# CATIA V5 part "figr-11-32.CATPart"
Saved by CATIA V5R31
Part number: Part1
Bounding box of the stored display mesh (mm): x -280 to 270, y -160 to 10, z 0 to 443
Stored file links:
  D:\PROJECTS\Project 2021\US EDITION\CATIA V5 6R 2021\Resources\Part Files\c11_catia_v5_6r2021_prt\figr-11-32.CATPart
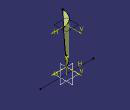
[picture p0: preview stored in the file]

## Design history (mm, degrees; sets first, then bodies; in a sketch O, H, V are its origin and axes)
Set1
  Plane1: type Offset, RefPlane xy-plane, Offset 443
  Sketch1 on Plane1, origin (0, 0, 443), H (1, 0, 0), V (0, 1, 0)
    arc A1 centre (51.3551, -160.9813) radius 171.358 from (40, 10) to (-120, -160) ccw
  Loft1: Sections (Sketch3; Sketch1)
  Sketch2 on zx-plane, origin (0, 0, 0), H (-1, 0, 0), V (0, 0, 1)
    line L1 (-270, 0) -> (280, 0)
    point P1 (-270, 0)
    coincidence: P1 H
    horizontal: L1 H
Body1 (main body)
  Sketch3 on Plane2, origin (0, 0, 67), H (1, 0, 0), V (0, 1, 0)
    point P1 (-100, 0)
    arc A1 centre (50, -150) radius 158.1139 from (0, 0) to (-100, -100) ccw
Set2
  Plane2: type Offset, RefPlane xy-plane, Offset 67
